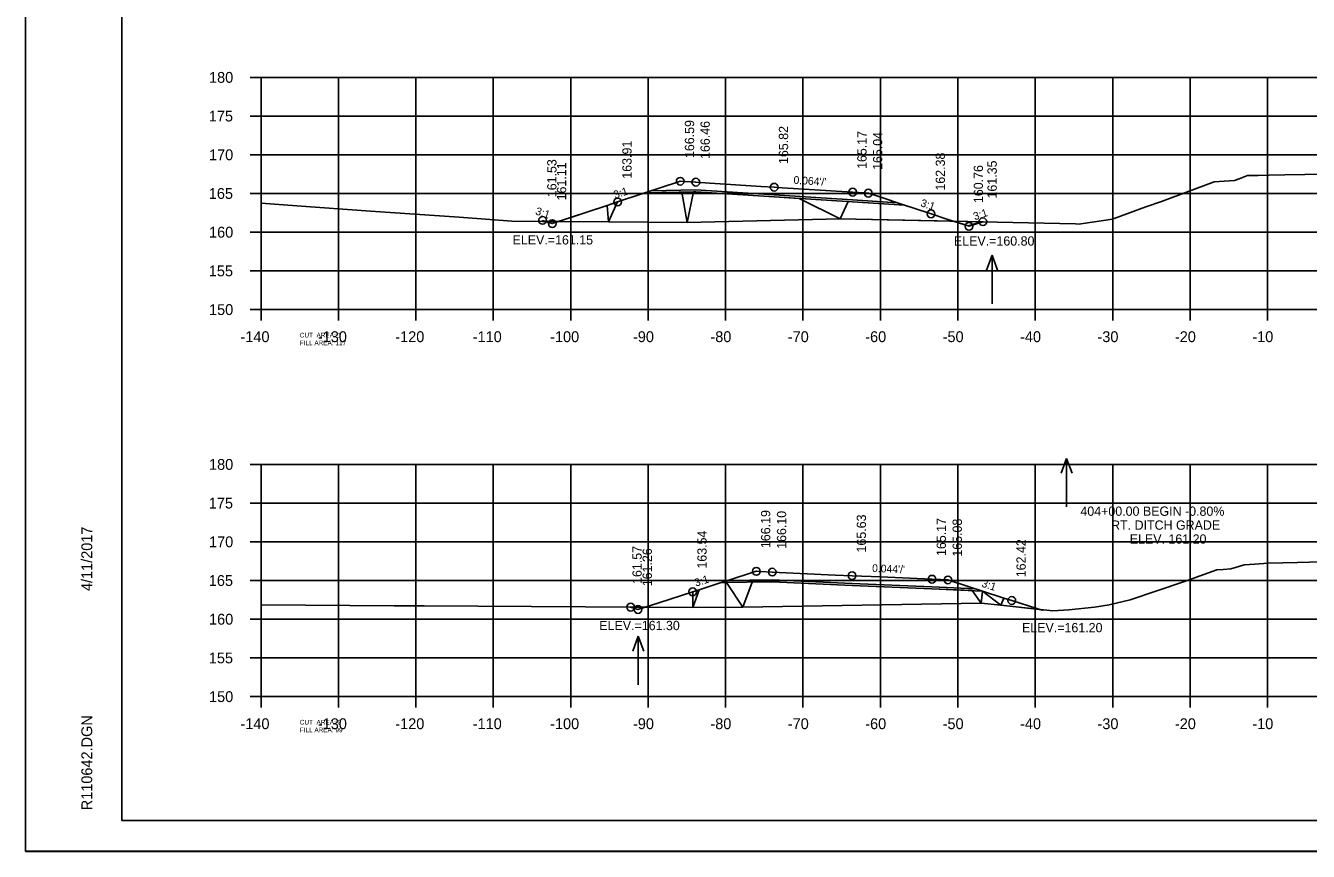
# Model space of a CAD drawing. Extents: x 1368503 to 1373085, y 379840 to 381833.
# Drawn here: x 1368502.7 to 1368668.3, y 380339.4 to 380446.1 of the extents above; entities that cross this region are included whole.
import ezdxf

# ---------------------------------------------------------------- set-up
doc = ezdxf.new("R2010")
doc.units = 0
for name, color, linetype in [('S_BRIDGE', 7, 'Continuous'), ('S_EDGE_PAVEMENT', 7, 'Continuous'), ('S_GRAVEL_ROAD', 7, 'Continuous'), ('S_MISC_BOUNDARY', 7, 'Continuous'), ('S_OBSCURES', 7, 'Continuous'), ('S_PHOTO_CENTERS', 7, 'Continuous'), ('S_PHOTO_NOTES', 7, 'Continuous'), ('S_RDW_PT_SYM', 7, 'Continuous'), ('S_SHOULDER', 7, 'Continuous'), ('S_STREAM_ANNOT', 7, 'Continuous'), ('S_TRAILS', 7, 'Continuous'), ('S_TREE', 7, 'Continuous')]:
    doc.layers.add(name, color=color, linetype=linetype)

msp = doc.modelspace()

# ---------------------------------------------------------------- linework, layer by layer
at = {"layer": 'S_BRIDGE'}
for p, q in [((1368515.06, 380343.37), (1368515.06, 380548.83)), ((1368515.06, 380343.37), (1368515.06, 380343.37)), ((1368831.24, 380343.37), (1368515.06, 380343.37))]:
    msp.add_line(p, q, dxfattribs=at)
at = {"layer": 'S_EDGE_PAVEMENT'}
for p, q in [((1368531.66, 380439.37), (1368533.06, 380439.37)), ((1368533.06, 380409.37), (1368533.06, 380439.37)), ((1368531.66, 380434.37), (1368533.06, 380434.37)), ((1368531.66, 380429.37), (1368533.06, 380429.37)), ((1368531.66, 380424.37), (1368533.06, 380424.37)), ((1368531.66, 380419.37), (1368533.06, 380419.37)), ((1368531.66, 380414.37), (1368533.06, 380414.37)), ((1368531.66, 380409.37), (1368533.06, 380409.37)), ((1368533.06, 380409.37), (1368813.06, 380409.37)), ((1368533.06, 380407.97), (1368533.06, 380409.37)), ((1368543.06, 380407.97), (1368543.06, 380409.37)), ((1368553.06, 380407.97), (1368553.06, 380409.37)), ((1368563.06, 380407.97), (1368563.06, 380409.37)), ((1368573.06, 380407.97), (1368573.06, 380409.37)), ((1368583.06, 380407.97), (1368583.06, 380409.37)), ((1368593.06, 380407.97), (1368593.06, 380409.37)), ((1368603.06, 380407.97), (1368603.06, 380409.37)), ((1368613.06, 380407.97), (1368613.06, 380409.37)), ((1368623.06, 380407.97), (1368623.06, 380409.37)), ((1368633.06, 380407.97), (1368633.06, 380409.37)), ((1368643.06, 380407.97), (1368643.06, 380409.37)), ((1368653.06, 380407.97), (1368653.06, 380409.37)), ((1368663.06, 380407.97), (1368663.06, 380409.37)), ((1368531.66, 380389.37), (1368533.06, 380389.37)), ((1368533.06, 380359.37), (1368533.06, 380389.37)), ((1368531.66, 380384.37), (1368533.06, 380384.37)), ((1368531.66, 380379.37), (1368533.06, 380379.37)), ((1368531.66, 380374.37), (1368533.06, 380374.37)), ((1368531.66, 380369.37), (1368533.06, 380369.37)), ((1368531.66, 380364.37), (1368533.06, 380364.37)), ((1368531.66, 380359.37), (1368533.06, 380359.37)), ((1368533.06, 380359.37), (1368813.06, 380359.37)), ((1368533.06, 380357.97), (1368533.06, 380359.37)), ((1368543.06, 380357.97), (1368543.06, 380359.37)), ((1368553.06, 380357.97), (1368553.06, 380359.37)), ((1368563.06, 380357.97), (1368563.06, 380359.37)), ((1368573.06, 380357.97), (1368573.06, 380359.37)), ((1368583.06, 380357.97), (1368583.06, 380359.37)), ((1368593.06, 380357.97), (1368593.06, 380359.37)), ((1368603.06, 380357.97), (1368603.06, 380359.37)), ((1368613.06, 380357.97), (1368613.06, 380359.37)), ((1368623.06, 380357.97), (1368623.06, 380359.37)), ((1368633.06, 380357.97), (1368633.06, 380359.37)), ((1368643.06, 380357.97), (1368643.06, 380359.37)), ((1368653.06, 380357.97), (1368653.06, 380359.37)), ((1368663.06, 380357.97), (1368663.06, 380359.37))]:
    msp.add_line(p, q, dxfattribs=at)
at = {"layer": 'S_GRAVEL_ROAD'}
for p, q in [((1368627.48, 380416.4), (1368626.78, 380414.48)), ((1368627.48, 380410.12), (1368627.48, 380416.4)), ((1368627.48, 380416.4), (1368628.18, 380414.48)), ((1368637.11, 380390.15), (1368636.41, 380388.23)), ((1368637.11, 380383.87), (1368637.11, 380390.15)), ((1368637.11, 380390.15), (1368637.81, 380388.23)), ((1368581.79, 380367.18), (1368581.09, 380365.25)), ((1368581.79, 380360.89), (1368581.79, 380367.18)), ((1368581.79, 380367.18), (1368582.49, 380365.25))]:
    msp.add_line(p, q, dxfattribs=at)
at = {"layer": 'S_MISC_BOUNDARY'}
for points in [[(1368533.06, 380423.1), (1368537.66, 380422.78), (1368547.21, 380422.1), (1368558.64, 380421.29), (1368565.46, 380420.79), (1368577.92, 380420.69), (1368588.08, 380420.62), (1368607.84, 380421.11), (1368638.25, 380420.47), (1368638.73, 380420.41), (1368638.95, 380420.45), (1368643.02, 380421.05), (1368643.25, 380421.13), (1368647.36, 380422.63), (1368649.35, 380423.35), (1368656.17, 380425.88), (1368658.12, 380425.99), (1368658.79, 380426.06), (1368659.4, 380426.28), (1368660.47, 380426.7), (1368661.84, 380426.71), (1368663.28, 380426.74), (1368665.28, 380426.78), (1368673.04, 380426.93)], [(1368533.06, 380371.22), (1368550.27, 380371.12), (1368554.14, 380371.09), (1368588.82, 380370.89), (1368595.27, 380370.94), (1368626.08, 380371.45), (1368628.63, 380371.18), (1368635.33, 380370.44), (1368637.39, 380370.59), (1368640.73, 380370.93), (1368642.59, 380371.22), (1368645.34, 380371.86), (1368652.2, 380374.19), (1368656.52, 380375.74), (1368657.32, 380375.78), (1368658.33, 380375.88), (1368659.36, 380376.18), (1368660.05, 380376.4), (1368661.42, 380376.48), (1368663.15, 380376.6), (1368666.94, 380376.71), (1368673.09, 380376.86)]]:
    msp.add_lwpolyline(points, dxfattribs=at)
at = {"layer": 'S_OBSCURES'}
for points in [[(1368616.19, 380422.86), (1368609.47, 380423.29), (1368599.34, 380423.93), (1368589.22, 380424.58), (1368582.63, 380424.44)], [(1368615.25, 380423.17), (1368609.47, 380423.54), (1368599.34, 380424.18), (1368589.22, 380424.83), (1368583.44, 380424.71)], [(1368626.23, 380373.01), (1368619.72, 380373.29), (1368609.4, 380373.74), (1368599.09, 380374.21), (1368592.49, 380374.1)], [(1368625.34, 380373.3), (1368619.72, 380373.54), (1368609.4, 380373.99), (1368599.09, 380374.46), (1368593.31, 380374.36)]]:
    msp.add_lwpolyline(points, dxfattribs=at)
at = {"layer": 'S_PHOTO_CENTERS'}
for p, q in [((1368533.06, 380439.37), (1368813.06, 380439.37)), ((1368533.06, 380409.37), (1368533.06, 380439.37)), ((1368543.06, 380409.37), (1368543.06, 380439.37)), ((1368553.06, 380409.37), (1368553.06, 380439.37)), ((1368563.06, 380409.37), (1368563.06, 380439.37)), ((1368573.06, 380409.37), (1368573.06, 380439.37)), ((1368583.06, 380409.37), (1368583.06, 380439.37)), ((1368593.06, 380409.37), (1368593.06, 380439.37)), ((1368603.06, 380409.37), (1368603.06, 380439.37)), ((1368613.06, 380409.37), (1368613.06, 380439.37)), ((1368623.06, 380409.37), (1368623.06, 380439.37)), ((1368633.06, 380409.37), (1368633.06, 380439.37)), ((1368643.06, 380409.37), (1368643.06, 380439.37)), ((1368653.06, 380409.37), (1368653.06, 380439.37)), ((1368663.06, 380409.37), (1368663.06, 380439.37)), ((1368533.06, 380434.37), (1368813.06, 380434.37)), ((1368533.06, 380429.37), (1368813.06, 380429.37)), ((1368533.06, 380424.37), (1368813.06, 380424.37)), ((1368533.06, 380419.37), (1368813.06, 380419.37)), ((1368533.06, 380414.37), (1368813.06, 380414.37)), ((1368533.06, 380409.37), (1368813.06, 380409.37)), ((1368533.06, 380389.37), (1368813.06, 380389.37)), ((1368533.06, 380359.37), (1368533.06, 380389.37)), ((1368543.06, 380359.37), (1368543.06, 380389.37)), ((1368553.06, 380359.37), (1368553.06, 380389.37)), ((1368563.06, 380359.37), (1368563.06, 380389.37)), ((1368573.06, 380359.37), (1368573.06, 380389.37)), ((1368583.06, 380359.37), (1368583.06, 380389.37)), ((1368593.06, 380359.37), (1368593.06, 380389.37)), ((1368603.06, 380359.37), (1368603.06, 380389.37)), ((1368613.06, 380359.37), (1368613.06, 380389.37)), ((1368623.06, 380359.37), (1368623.06, 380389.37)), ((1368633.06, 380359.37), (1368633.06, 380389.37)), ((1368643.06, 380359.37), (1368643.06, 380389.37)), ((1368653.06, 380359.37), (1368653.06, 380389.37)), ((1368663.06, 380359.37), (1368663.06, 380389.37)), ((1368533.06, 380384.37), (1368813.06, 380384.37)), ((1368533.06, 380379.37), (1368813.06, 380379.37)), ((1368533.06, 380374.37), (1368813.06, 380374.37)), ((1368533.06, 380369.37), (1368813.06, 380369.37)), ((1368533.06, 380364.37), (1368813.06, 380364.37)), ((1368533.06, 380359.37), (1368813.06, 380359.37))]:
    msp.add_line(p, q, dxfattribs=at)
at = {"layer": 'S_PHOTO_NOTES'}
msp.add_line((1368502.66, 380339.39), (1368835.99, 380339.39), dxfattribs=at)
for points in [[(1368502.65, 380552.72), (1368835.99, 380552.72), (1368835.99, 380339.38), (1368502.65, 380339.38)], [(1368748.98, 380548.83), (1368748.98, 380538.95), (1368784.71, 380538.95), (1368784.71, 380536.03), (1368807.91, 380536.03), (1368807.91, 380511.69), (1368831.24, 380511.69), (1368831.24, 380343.37), (1368515.06, 380343.37), (1368515.06, 380548.83)], [(1368577.92, 380420.69), (1368588.08, 380420.62), (1368587.43, 380424.54), (1368582.63, 380424.44), (1368582.24, 380424.31), (1368579.12, 380423.28)], [(1368588.08, 380420.62), (1368607.84, 380421.11), (1368602.58, 380423.73), (1368599.34, 380423.93), (1368589.22, 380424.58), (1368588.91, 380424.57)], [(1368571.46, 380420.74), (1368577.92, 380420.69), (1368577.76, 380422.83)], [(1368607.84, 380421.11), (1368622.46, 380420.8), (1368621.65, 380421.07), (1368619.6, 380421.74), (1368617.39, 380422.47), (1368616.19, 380422.86), (1368609.47, 380423.29), (1368608.89, 380423.32)], [(1368569.42, 380420.89), (1368569.42, 380420.76), (1368569.84, 380420.75)], [(1368569.84, 380420.75), (1368571.46, 380420.74), (1368570.67, 380420.48), (1368570.07, 380420.68)], [(1368622.46, 380420.8), (1368626.29, 380420.72), (1368625.22, 380420.36), (1368624.51, 380420.13)], [(1368588.82, 380370.89), (1368595.27, 380370.94), (1368593.2, 380374.11), (1368592.49, 380374.1), (1368589.64, 380373.18)], [(1368595.27, 380370.94), (1368626.08, 380371.45), (1368624.9, 380373.07), (1368619.72, 380373.29), (1368609.4, 380373.74), (1368599.09, 380374.21), (1368596.5, 380374.17)], [(1368582.66, 380370.92), (1368588.82, 380370.89), (1368588.81, 380372.91), (1368584.46, 380371.5)], [(1368626.08, 380371.45), (1368628.63, 380371.18), (1368626.23, 380373.01)], [(1368628.63, 380371.18), (1368633.62, 380370.63), (1368633.28, 380370.74), (1368630.03, 380371.79), (1368629.02, 380372.11)], [(1368580.8, 380370.93), (1368580.8, 380370.93), (1368582.66, 380370.92), (1368581.74, 380370.63), (1368581.2, 380370.8)], [(1368633.62, 380370.63), (1368634.09, 380370.58), (1368633.94, 380370.53)]]:
    msp.add_lwpolyline(points, close=True, dxfattribs=at)
for centre in [(1368587.2, 380425.95), (1368589.22, 380425.83), (1368599.34, 380425.18), (1368579.12, 380423.28), (1368609.47, 380424.54), (1368611.5, 380424.41), (1368619.6, 380421.74), (1368569.42, 380420.89), (1368570.67, 380420.48), (1368624.51, 380420.13), (1368626.29, 380420.72), (1368597.03, 380375.56), (1368599.09, 380375.46), (1368609.4, 380374.99), (1368619.72, 380374.54), (1368621.78, 380374.45), (1368588.81, 380372.91), (1368630.03, 380371.79), (1368580.8, 380370.93), (1368581.74, 380370.63)]:
    msp.add_circle(centre, 0.5, dxfattribs=at)
at = {"layer": 'S_STREAM_ANNOT'}
for points in [[(1368569.42, 380420.89), (1368570.07, 380420.68), (1368570.67, 380420.48), (1368577.76, 380422.83), (1368579.12, 380423.28), (1368582.24, 380424.31), (1368582.63, 380424.44), (1368586.97, 380425.88), (1368587.2, 380425.95), (1368589.18, 380425.83), (1368589.22, 380425.83), (1368591.02, 380425.71), (1368594.35, 380425.5), (1368597.66, 380425.29), (1368599.34, 380425.18), (1368599.69, 380425.16), (1368609.47, 380424.54), (1368611.03, 380424.44), (1368611.5, 380424.41), (1368612.72, 380424.01), (1368616.19, 380422.86), (1368617.39, 380422.47), (1368619.6, 380421.74), (1368621.65, 380421.07), (1368624.51, 380420.13), (1368625.22, 380420.36), (1368626.29, 380420.72)], [(1368580.8, 380370.93), (1368581.2, 380370.8), (1368581.74, 380370.63), (1368584.46, 380371.5), (1368588.81, 380372.91), (1368589.64, 380373.18), (1368592.49, 380374.1), (1368593.08, 380374.29), (1368597.03, 380375.56), (1368597.06, 380375.56), (1368597.57, 380375.53), (1368599.09, 380375.46), (1368607.21, 380375.08), (1368609.4, 380374.99), (1368613.05, 380374.84), (1368619.72, 380374.54), (1368620.82, 380374.49), (1368621.78, 380374.45), (1368624.54, 380373.56), (1368626.23, 380373.01), (1368629.02, 380372.11), (1368630.03, 380371.79), (1368633.28, 380370.74), (1368633.94, 380370.53), (1368634.09, 380370.58)]]:
    msp.add_lwpolyline(points, dxfattribs=at)
at = {"layer": 'S_TREE'}
for q in [(1368622.67, 380420.73), (1368626.09, 380420.72)]:
    msp.add_line((1368624.4, 380420.17), q, dxfattribs=at)

# ---------------------------------------------------------------- texts
at = {"layer": 'S_BRIDGE'}
for s, p in [('4/11/2017', (1368511.25, 380373.01)), ('R110642.DGN', (1368511.25, 380344.69))]:
    msp.add_text(s, height=1.4, rotation=90, dxfattribs=at).set_placement(p)
at = {"layer": 'S_GRAVEL_ROAD'}
for s, p in [('ELEV.=161.15', (1368565.55, 380417.78)), ('ELEV.=160.80', (1368622.56, 380417.64)), ('404+00.00 BEGIN -0.80%', (1368638.89, 380382.73)), ('RT. DITCH GRADE', (1368642.86, 380380.93)), ('ELEV. 161.20', (1368645.27, 380379.13)), ('ELEV.=161.30', (1368576.75, 380367.96)), ('ELEV.=161.20', (1368631.35, 380367.69))]:
    msp.add_text(s, height=1.2, dxfattribs=at).set_placement(p)
at = {"layer": 'S_RDW_PT_SYM'}
for s, rotation, p in [('3:1', 18.3243, (1368578.78, 380423.69)), ("0.064'/'", 356.3597, (1368601.81, 380425.63)), ('3:1', 341.7947, (1368618.16, 380422.74)), ('3:1', 341.7224, (1368568.42, 380421.69)), ('3:1', 18.3443, (1368625.24, 380420.9)), ("0.044'/'", 357.4979, (1368611.97, 380375.48)), ('3:1', 17.8804, (1368589.23, 380373.57)), ('3:1', 342.1052, (1368626.06, 380373.59))]:
    msp.add_text(s, height=1, rotation=rotation, dxfattribs=at).set_placement(p)
at = {"layer": 'S_SHOULDER'}
for s, p in [('166.59', (1368589, 380428.95)), ('166.46', (1368591.02, 380428.83)), ('165.82', (1368601.14, 380428.18)), ('165.17', (1368611.27, 380427.54)), ('165.04', (1368613.3, 380427.41)), ('163.91', (1368580.92, 380426.28)), ('161.53', (1368571.22, 380423.89)), ('162.38', (1368621.4, 380424.74)), ('161.35', (1368628.09, 380423.72)), ('161.11', (1368572.47, 380423.48)), ('160.76', (1368626.31, 380423.13)), ('166.19', (1368598.83, 380378.56)), ('166.10', (1368600.89, 380378.46)), ('165.63', (1368611.2, 380377.99)), ('165.17', (1368621.52, 380377.54)), ('165.08', (1368623.58, 380377.45)), ('163.54', (1368590.61, 380375.91)), ('161.57', (1368582.23, 380373.93)), ('162.42', (1368631.83, 380374.79)), ('161.26', (1368583.54, 380373.63))]:
    msp.add_text(s, height=1.2, rotation=90, dxfattribs=at).set_placement(p)
at = {"layer": 'S_TRAILS'}
for s, height, p in [('180', 1.4, (1368526.34, 380438.67)), ('175', 1.4, (1368526.31, 380433.67)), ('170', 1.4, (1368526.34, 380428.67)), ('165', 1.4, (1368526.31, 380423.67)), ('160', 1.4, (1368526.34, 380418.67)), ('155', 1.4, (1368526.31, 380413.67)), ('150', 1.4, (1368526.34, 380408.67)), ('-140', 1.4, (1368530.4, 380405.17)), ('CUT  AREA: 1', 0.6, (1368538.06, 380405.77)), ('FILL AREA: 117', 0.6, (1368538.06, 380404.77)), ('-130', 1.4, (1368540.4, 380405.17)), ('-120', 1.4, (1368550.4, 380405.17)), ('-110', 1.4, (1368560.4, 380405.17)), ('-100', 1.4, (1368570.4, 380405.17)), ('-90', 1.4, (1368581.1, 380405.17)), ('-80', 1.4, (1368591.1, 380405.17)), ('-70', 1.4, (1368601.1, 380405.17)), ('-60', 1.4, (1368611.1, 380405.17)), ('-50', 1.4, (1368621.1, 380405.17)), ('-40', 1.4, (1368631.1, 380405.17)), ('-30', 1.4, (1368641.1, 380405.17)), ('-20', 1.4, (1368651.1, 380405.17)), ('-10', 1.4, (1368661.1, 380405.17)), ('180', 1.4, (1368526.34, 380388.67)), ('175', 1.4, (1368526.31, 380383.67)), ('170', 1.4, (1368526.34, 380378.67)), ('165', 1.4, (1368526.31, 380373.67)), ('160', 1.4, (1368526.34, 380368.67)), ('155', 1.4, (1368526.31, 380363.67)), ('150', 1.4, (1368526.34, 380358.67)), ('-140', 1.4, (1368530.4, 380355.17)), ('CUT  AREA: 0', 0.6, (1368538.06, 380355.77)), ('-130', 1.4, (1368540.4, 380355.17)), ('-120', 1.4, (1368550.4, 380355.17)), ('-110', 1.4, (1368560.4, 380355.17)), ('-100', 1.4, (1368570.4, 380355.17)), ('-90', 1.4, (1368581.1, 380355.17)), ('-80', 1.4, (1368591.1, 380355.17)), ('-70', 1.4, (1368601.1, 380355.17)), ('-60', 1.4, (1368611.1, 380355.17)), ('-50', 1.4, (1368621.1, 380355.17)), ('-40', 1.4, (1368631.1, 380355.17)), ('-30', 1.4, (1368641.1, 380355.17)), ('-20', 1.4, (1368651.1, 380355.17)), ('-10', 1.4, (1368661.1, 380355.17)), ('FILL AREA: 99', 0.6, (1368538.06, 380354.77))]:
    msp.add_text(s, height=height, dxfattribs=at).set_placement(p)

doc.saveas('drawing.dxf')
